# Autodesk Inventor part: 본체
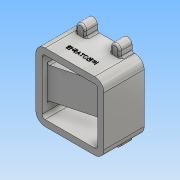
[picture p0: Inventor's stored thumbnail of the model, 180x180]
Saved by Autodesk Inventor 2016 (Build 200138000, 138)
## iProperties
Created: 2018-01
Part Number: 본체
Material: 알루미늄 6061
Document SubType Name: Modeling
Designer: Administrator
Mass: 994.428 g
Surface Area: 845.509 cm^2
Volume: 368.307 cm^3
Density: 2.7 g/cm^3
Appearance: 알루미늄 - 평지
Author: Administrator
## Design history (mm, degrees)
sketch "스케치2"
  geometry: L1 (40, -55)-(-40, -55); L2 (-55, -40)-(-55, 40); L3 (-40, 55)-(40, 55); L4 (55, 40)-(55, -40); L5 (0, 55)-(0, -55); L6 (55, 0)-(-55, 0); A1 r 15 centre (40, -40) between (40, -55) and (55, -40); A2 r 15 centre (-40, -40) between (-55, -40) and (-40, -55); A3 r 15 centre (-40, 40) between (-40, 55) and (-55, 40); A4 r 15 centre (40, 40) between (55, 40) and (40, 55); 5 further points
  constraints: 12 end point, 8 point on circle, 8 tangent, 6 point on line, 5 midpoint, 4 centre point, 3 equal radius, 2 parallel, 1 coincident, 1 horizontal, 1 perpendicular
  dimensions: "d0" = 110 distance of point (-55, 55) point (55, 55); "d1" = 110 distance of point (-55, -55) point (-55, 55); "d2" = 15 radius of A1
extrude "돌출1" new body sketch "스케치2" distance "d3" = 65; taper "d4" = 0 deg
sketch "스케치3"
  geometry: L1 (40, 55)-(-40, 55) reference; L2 (-55, 40)-(-55, -40) reference; L3 (-35.5, 65)-(-35.5, 50.607); L4 (-35.5, 50.607)-(-20.5, 50.607); L5 (-20.5, 50.607)-(-20.5, 65); L6 (20.5, 65)-(20.5, 49.182); L7 (20.5, 49.182)-(35.5, 49.182); L8 (35.5, 49.182)-(35.5, 65); A1 r 7.5 centre (-28, 65) between (-20.5, 65) and (-35.5, 65); A2 r 7.5 centre (28, 65) between (35.5, 65) and (20.5, 65); 1 further point
  constraints: 12 end point, 4 point on circle, 2 centre point, 2 perpendicular, 2 tangent, 2 vertical
  dimensions: "d5" = 15 diameter of A1; "d6" = 15 diameter of A2; "d7" = 56 distance of A1.centre A2.centre; "d8" = 27 distance from line of A1.centre L2; "d9" = 10 distance from line of A1.centre L1; "d11" = 10 distance from line of L1 A2.centre; "d12" = 15 distance of L3.end L4.end; "d13" = 15 distance of L6.end L7.end; "d14" = 14.3934 distance of L4.end L5.end; "d15" = 14.3934 distance of L3.start L3.end; "d16" = 80 distance of L1.start L1.end (derived); "d17" = 15.81759 distance of L6.start L6.end; "d18" = 15.81759 distance of L7.end L8.end
extrude "돌출2" join sketch "스케치3" distance "d19" = 20; taper "d20" = 0 deg
sketch "스케치4"
  geometry: A1 r 7.5 centre (-28, 65) between (-20.5, 65) and (-35.5, 65) reference; 2 further points
  constraints: 1 coincident
hole "구멍1" sketch "스케치4" at (-28, 65) diameter "d21" = 3.242; stored, may be unused: countersink angle "d25" = 90 deg, drill point angle "d27" = 118 deg; dims "d22" = 8, "d23" = 4, "d24" = 2, "d26" = 11
node "작업 평면1"
sketch "스케치5"
  geometry: L1 (-15, 0)-(-15, 65) reference; L2 (95, 0)-(80, 0) reference; 2 further points
  constraints: 1 other
  dimensions: "d35" = 55 distance from line of L1 point (40, 20); "d36" = 20 distance from line of L2 point (40, 20)
feature "엠보싱1" sketch "스케치5" dims "d0" = 110, "d1" = 110, "d2" = 15, "d5" = 15, "d6" = 15, "d7" = 56, "d8" = 27, "d9" = 10, "d11" = 10, "d12" = 15, "d13" = 15, "d14" = 14.3934, "d15" = 14.3934, "d17" = 15.81759, "d18" = 15.81759, "d37" = 0.5, "d38" = 0
sketch "스케치6"
  geometry: L1 (55, -40)-(55, 40) reference; L2 (20.5, 55)-(-20.5, 55) reference; L3 (-55, 40)-(-55, -40) reference; L4 (-20.5, -55)-(20.5, -55) reference; L5 (-45, 45)-(45, 45); L6 (45, 54.142)-(45, -45); L7 (45, -45)-(-45, -45); L8 (-45, -45)-(-45, -25); L9 (-45, -25)-(35, -25); L10 (35, -25)-(35, 25); L11 (35, 25)-(-45, 25); L12 (-45, 25)-(-45, 45); A1 r 15 centre (40, -40) between (40, -55) and (55, -40) reference; A2 r 15 centre (40, 40) between (55, 40) and (40, 55) reference; A3 r 15 centre (-40, 40) between (-40, 55) and (-55, 40) reference; A4 r 15 centre (-40, -40) between (-55, -40) and (-40, -55) reference; 8 further points
  constraints: 16 end point, 6 perpendicular, 5 point on line, 4 point on circle, 1 horizontal, 1 parallel
  dimensions: "d39" = 10 distance between parallel lines of L7 L4; "d40" = 10 distance between parallel lines of L2 L5; "d41" = 30 distance between parallel lines of L11 L2; "d42" = 10 distance between parallel lines of L1 L6; "d43" = 20 distance between parallel lines of L1 L10; "d44" = 30 distance between parallel lines of L4 L9; "d45" = 10 distance from line of L3.end L8; "d46" = 10 distance between parallel lines of L3 L12
extrude "돌출3" cut sketch "스케치6" stored distance "d55" = 20; taper "d56" = 0 deg
sketch "스케치7"
  geometry: L1 (77, -65)-(-3, -65) reference; L2 (-3, -56.436)-(77, -35); L3 (97, -65)-(97, 0) reference; L4 (-13, -65)-(-13, 0) reference; L5 (-3, -56.436)-(-3, -72.207); L6 (77, -35)-(77, -72.207); L7 (77, -72.207)-(-3, -72.207); 3 further points
  constraints: 8 end point, 2 vertical, 1 perpendicular
  dimensions: "d59" = 30 distance from line of L1 L2.end; "d61" = 10 distance between parallel lines of L4 L5; "d62" = 105 deg angle of L2 L5; "d63" = 20 distance from line of L3 L6.end; "d65" = 37.20743 distance of L2.end L6.end
extrude "돌출4" cut sketch "스케치7" distance "d66" = 50; taper "d67" = 0 deg
sketch "스케치9"
  geometry: L1 (-40, 65)-(-55, 65) reference; L2 (-55, 65)-(30, 65); L3 (-40, 65)-(45, 65) reference; L4 (30, 65)-(30, 50); L5 (30, 50)-(25, 50); L6 (25, 50)-(25, 45); L7 (25, 45)-(-22, 45); L8 (-22, 45)-(-22, 49); L9 (-22, 49)-(-36, 49); L10 (-55, 0)-(-55, 65) reference; L11 (-36, 49)-(-36, 57.5); L12 (-36, 57.5)-(-55, 57.5); L13 (-55, 65)-(-55, 57.5); 2 further points
  constraints: 20 end point, 6 perpendicular, 2 point on line, 2 vertical, 1 collinear
  dimensions: "d78" = 7.5 distance between parallel lines of L1 L12; "d79" = 16 distance from line of L2 L9.end; "d80" = 20 distance from line of L2 L7.end; "d81" = 15 distance of L2.end L4.end; "d82" = 5 distance of L4.end L5.end; "d83" = 47 distance of L6.end L7.end; "d84" = 19 distance of L11.end L12.end; "d85" = 14 distance of L8.end L9.end
revolve "회전1" sketch "스케치9" stored, may be unused: angle "d86" = 90 deg
chamfer "모따기1" distance "d87" = 1; stored, may be unused: second distance "d88" = 2, angle "d89" = 45 deg
sketch "스케치10"
  geometry: L1 (-55, 0)-(-55, 65) reference; L2 (35, 30)-(-45, 8.564) reference; L3 (20, 31.157)-(-55, 11.061); L4 (-55, 11.061)-(-55, 29.061); L5 (-55, 29.061)-(-17, 39.243); L6 (-17, 39.243)-(-17, 54.361); L7 (-17, 54.361)-(20, 54.361); L8 (20, 54.361)-(20, 31.157); L9 (-22, 49)-(-22, 65) reference; 3 further points
  constraints: 12 end point, 2 parallel, 2 perpendicular, 2 point on line
  dimensions: "d90" = 5 distance between parallel lines of L2 L3; "d91" = 37 distance of L6.end L7.end; "d92" = 75 deg angle of L1 L5; "d93" = 18 distance of L3.end L4.end; "d94" = 5 distance between parallel lines of L9 L6; "d95" = 23.20373 distance of L7.end L3.start
extrude "돌출5" cut sketch "스케치10" stored distance "d96" = 30; taper "d97" = 0 deg
fillet "모깎기1" dims "d98" = 5
fillet "모깎기2" dims "d99" = 3
fillet "모깎기3" dims "d100" = 3
node "솔리드1"
mirror "대칭1"
pattern_linear "직사각형 패턴1" dims "d30" = 56
other parameters: "d34" = 39
